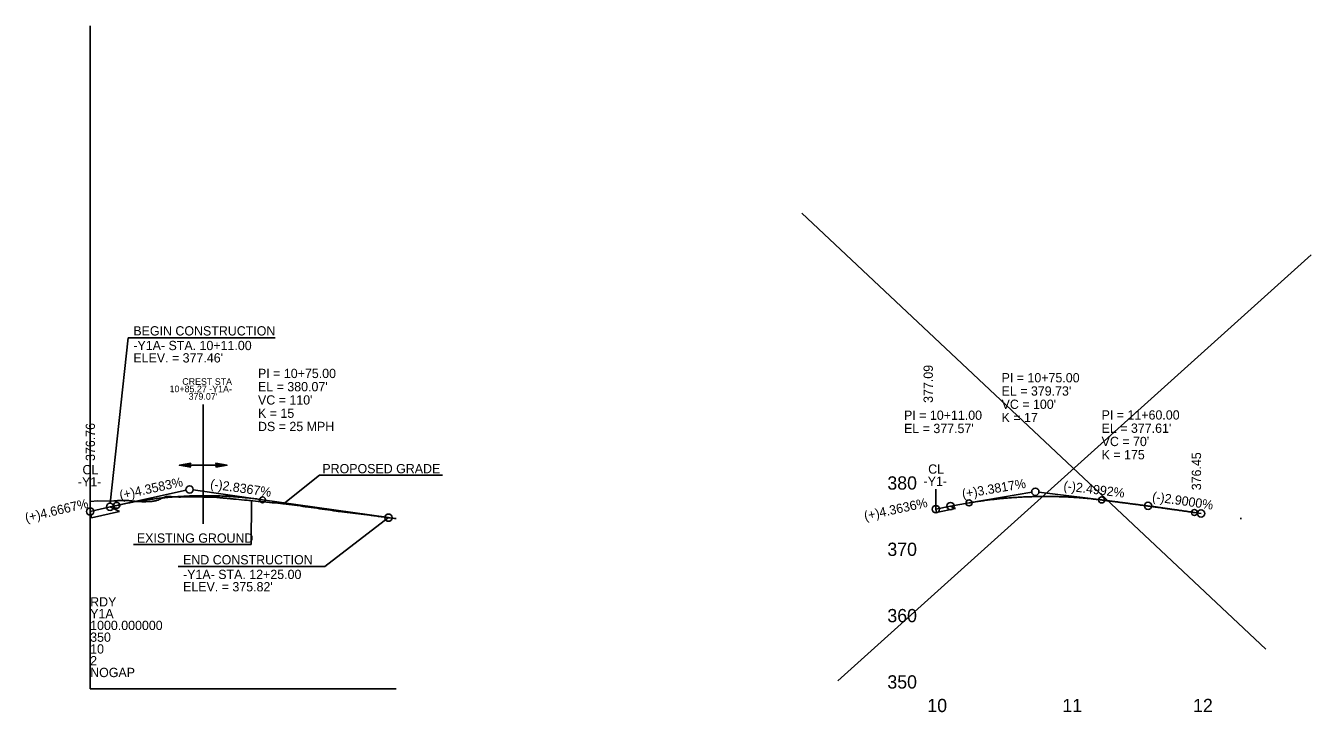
# Model space of a CAD drawing. Extents: x 1625686 to 1640492, y 1161393 to 1175642.
# Drawn here: x 1630156 to 1631125, y 1170769 to 1171286 of the extents above; entities that cross this region are included whole.
import ezdxf

# ---------------------------------------------------------------- set-up
doc = ezdxf.new("R2010")
doc.units = 0
for name, color, linetype in [('Exist Profile Cell', 7, 'Continuous'), ('Exist Vertical Profile Ground Line', 7, 'Continuous'), ('Exist Vertical Profile Horizontal Axis Label Major', 7, 'Continuous'), ('Exist Vertical Profile Vertical Axis Label', 7, 'Continuous'), ('Prop Plan Preparation Crest', 7, 'Continuous'), ('Prop Vertical Profile Curve Label', 7, 'Continuous'), ('Prop Vertical Profile Grade', 7, 'Continuous'), ('Prop Vertical Profile Grade Label', 7, 'Continuous'), ('Prop VPI Label', 7, 'Continuous')]:
    doc.layers.add(name, color=color, linetype=linetype)

msp = doc.modelspace()

# ---------------------------------------------------------------- linework, layer by layer
at = {"layer": 'Exist Profile Cell'}
for q in [(1630204.31, 1171286.24), (1630434.97, 1170786.24), (1630204.31, 1170786.24)]:
    msp.add_line((1630204.31, 1170786.24), q, dxfattribs=at)
at = {"layer": 'Exist Vertical Profile Ground Line'}
for points in [[(1630204.31, 1170927.62), (1630210.19, 1170927.9), (1630220.57, 1170927.84), (1630222.12, 1170927.94), (1630222.92, 1170927.99), (1630223.71, 1170928.04), (1630224.51, 1170928.1), (1630225.3, 1170928.15), (1630225.61, 1170928.17), (1630226.1, 1170928.19), (1630226.89, 1170928.22), (1630227.69, 1170928.25), (1630228.48, 1170928.29), (1630229.28, 1170928.32), (1630230.07, 1170928.35), (1630230.96, 1170928.39), (1630231.66, 1170928.32), (1630232.46, 1170928.23), (1630233.25, 1170928.15), (1630234.05, 1170928.07), (1630234.84, 1170927.98), (1630235.64, 1170927.9), (1630236.43, 1170927.82), (1630237.22, 1170927.73), (1630238.02, 1170927.65), (1630238.4, 1170927.61), (1630238.81, 1170927.6), (1630239.61, 1170927.58), (1630240.4, 1170927.56), (1630241.2, 1170927.53), (1630241.99, 1170927.48), (1630242.79, 1170927.42), (1630243.58, 1170927.38), (1630244.38, 1170927.38), (1630245.17, 1170927.39), (1630245.97, 1170927.39), (1630246.76, 1170927.4), (1630247.56, 1170927.4), (1630248.35, 1170927.4), (1630249.15, 1170927.41), (1630249.54, 1170927.41), (1630249.94, 1170927.47), (1630250.74, 1170927.59), (1630251.53, 1170927.71), (1630252.33, 1170927.83), (1630253.12, 1170927.95), (1630253.92, 1170928.07), (1630254.46, 1170928.15), (1630255.51, 1170928.62), (1630256.3, 1170928.97), (1630257.09, 1170929.32), (1630257.89, 1170929.66), (1630258.68, 1170930.01), (1630259.48, 1170930.35), (1630260.27, 1170930.68), (1630261.07, 1170931.02), (1630261.96, 1170931.35), (1630262.66, 1170931.31), (1630263.45, 1170931.28), (1630264.25, 1170931.24), (1630265.04, 1170931.2), (1630265.84, 1170931.16), (1630266.63, 1170931.13), (1630267.43, 1170931.09), (1630268.22, 1170931.05), (1630269.02, 1170931.02), (1630269.81, 1170930.98), (1630270.61, 1170930.94), (1630271.4, 1170930.91), (1630271.75, 1170930.89), (1630272.14, 1170930.88), (1630272.99, 1170930.94), (1630273.79, 1170930.99), (1630274.67, 1170931.04), (1630275.02, 1170931.06), (1630275.37, 1170931.06), (1630276.17, 1170931.06), (1630276.96, 1170931.05), (1630277.76, 1170931.04), (1630278.55, 1170931.04), (1630279.35, 1170931.03), (1630280.14, 1170931.03), (1630280.94, 1170931.02), (1630281.73, 1170931.01), (1630282.53, 1170931), (1630283.32, 1170931), (1630284.12, 1170930.99), (1630284.91, 1170930.98), (1630285.71, 1170930.97), (1630286.04, 1170930.97), (1630286.5, 1170930.96), (1630287.3, 1170930.95), (1630288.09, 1170930.93), (1630288.89, 1170930.92), (1630289.68, 1170930.91), (1630290.48, 1170930.89), (1630291.27, 1170930.88), (1630292.07, 1170930.87), (1630292.86, 1170930.85), (1630293.65, 1170930.84), (1630294.45, 1170930.82), (1630295.24, 1170930.81), (1630296.04, 1170930.79), (1630296.83, 1170930.78), (1630297.63, 1170930.76), (1630298.52, 1170930.73), (1630299.22, 1170930.67), (1630300.01, 1170930.59), (1630300.81, 1170930.51), (1630301.69, 1170930.42), (1630302.4, 1170930.36), (1630303.19, 1170930.29), (1630303.99, 1170930.22), (1630304.78, 1170930.15), (1630305.58, 1170930.07), (1630306.37, 1170930), (1630307.17, 1170929.93), (1630307.96, 1170929.85), (1630308.76, 1170929.78), (1630309.55, 1170929.7), (1630310.35, 1170929.63), (1630311.14, 1170929.55), (1630311.94, 1170929.48), (1630312.73, 1170929.4), (1630313.52, 1170929.33), (1630314.32, 1170929.25), (1630316.42, 1170929.05), (1630318.51, 1170928.84), (1630320.61, 1170928.64), (1630322.71, 1170928.44), (1630324.02, 1170928.31), (1630324.81, 1170928.23), (1630325.16, 1170928.19), (1630326.91, 1170928.02), (1630329, 1170927.82), (1630331.1, 1170927.62), (1630333.2, 1170927.42), (1630335.3, 1170927.22), (1630337.39, 1170927.02), (1630339.49, 1170926.83), (1630341.59, 1170926.63), (1630343.69, 1170926.43), (1630345.78, 1170926.23), (1630347.88, 1170926.04), (1630349, 1170925.93), (1630349.07, 1170925.93), (1630349.98, 1170925.81), (1630352.08, 1170925.53), (1630354.17, 1170925.26), (1630356.27, 1170924.99), (1630358.37, 1170924.71), (1630360.47, 1170924.42), (1630362.56, 1170924.13), (1630364.66, 1170923.84), (1630366.18, 1170923.64), (1630366.76, 1170923.56), (1630368.86, 1170923.27), (1630370.95, 1170922.98), (1630373.05, 1170922.69), (1630375.15, 1170922.4), (1630377.25, 1170922.11), (1630379.35, 1170921.82), (1630380.76, 1170921.62), (1630381.44, 1170921.52), (1630383.54, 1170921.22), (1630385.64, 1170920.92), (1630387.74, 1170920.61), (1630389.83, 1170920.3), (1630390.27, 1170920.24), (1630391.31, 1170920.06), (1630391.93, 1170919.99), (1630394.03, 1170919.75), (1630396.13, 1170919.5), (1630398.22, 1170919.25), (1630400.32, 1170919), (1630402.42, 1170918.74), (1630404.52, 1170918.49), (1630406.61, 1170918.23), (1630407.02, 1170918.18), (1630408.71, 1170917.96), (1630410.81, 1170917.7), (1630412.91, 1170917.43), (1630415, 1170917.17), (1630416.16, 1170917.02), (1630416.29, 1170917), (1630417.1, 1170916.9), (1630418.22, 1170916.76), (1630419.34, 1170916.62), (1630420.45, 1170916.47), (1630421.57, 1170916.33), (1630422.69, 1170916.18), (1630423.8, 1170916.04), (1630424.92, 1170915.89), (1630426.04, 1170915.75), (1630427.15, 1170915.6), (1630428.27, 1170915.46), (1630429.39, 1170915.31), (1630430.5, 1170915.17), (1630431.62, 1170915.02), (1630432.74, 1170914.9), (1630433.85, 1170914.76), (1630434.97, 1170914.62)], [(1631071.48, 1170914.76), (1631072.6, 1170914.62)]]:
    msp.add_lwpolyline(points, dxfattribs=at)
at = {"layer": 'Prop Plan Preparation Crest'}
for p, q in [((1630289.58, 1170910.79), (1630289.58, 1171000.74)), ((1630289.58, 1170954.88), (1630271.58, 1170954.88)), ((1630289.58, 1170954.88), (1630307.58, 1170954.88))]:
    msp.add_line(p, q, dxfattribs=at)
for points in [[(1630280.15, 1170953.46), (1630271.58, 1170954.88), (1630280.15, 1170956.31), (1630279.08, 1170954.88)], [(1630299.02, 1170953.46), (1630307.58, 1170954.88), (1630299.02, 1170956.31), (1630300.08, 1170954.88)]]:
    msp.add_lwpolyline(points, close=True, dxfattribs=at)
at = {"layer": 'Prop Vertical Profile Curve Label'}
for p, q in [((1630204.31, 1170921.24), (1630204.31, 1170936.44)), ((1630842.08, 1170921.69), (1630842.08, 1170936.89))]:
    msp.add_line(p, q, dxfattribs=at)
for centre in [(1630224.31, 1170924.63), (1630334.31, 1170928.82), (1630867.08, 1170926.46), (1630967.08, 1170928.67), (1631037.08, 1170919.22)]:
    msp.add_circle(centre, 2.25, dxfattribs=at)
at = {"layer": 'Prop Vertical Profile Grade'}
for p, q in [((1630334.31, 1170928.82), (1630429.31, 1170915.34)), ((1630853.08, 1170924.09), (1630867.08, 1170926.46)), ((1630204.31, 1170920.04), (1630219.31, 1170923.54)), ((1630219.31, 1170923.54), (1630224.31, 1170924.63)), ((1630842.08, 1170921.69), (1630853.08, 1170924.09)), ((1631037.08, 1170919.22), (1631042.08, 1170918.49))]:
    msp.add_line(p, q, dxfattribs=at)
for points in [[(1630224.31, 1170924.63), (1630226.51, 1170925.1), (1630228.71, 1170925.56), (1630230.91, 1170926), (1630233.11, 1170926.42), (1630235.31, 1170926.83), (1630237.51, 1170927.22), (1630239.71, 1170927.6), (1630241.91, 1170927.96), (1630244.11, 1170928.31), (1630246.31, 1170928.63), (1630248.51, 1170928.95), (1630250.71, 1170929.24), (1630252.91, 1170929.53), (1630255.11, 1170929.79), (1630257.31, 1170930.04), (1630259.51, 1170930.28), (1630261.71, 1170930.49), (1630263.91, 1170930.7), (1630266.11, 1170930.88), (1630268.31, 1170931.05), (1630270.51, 1170931.21), (1630272.71, 1170931.35), (1630274.91, 1170931.47), (1630277.11, 1170931.58), (1630279.31, 1170931.67), (1630281.51, 1170931.75), (1630283.71, 1170931.81), (1630285.91, 1170931.85), (1630288.11, 1170931.88), (1630290.31, 1170931.89), (1630292.51, 1170931.89), (1630294.71, 1170931.87), (1630296.91, 1170931.83), (1630299.11, 1170931.78), (1630301.31, 1170931.72), (1630303.51, 1170931.63), (1630305.71, 1170931.54), (1630307.91, 1170931.42), (1630310.11, 1170931.29), (1630312.31, 1170931.15), (1630314.51, 1170930.98), (1630316.71, 1170930.81), (1630318.91, 1170930.61), (1630321.11, 1170930.4), (1630323.31, 1170930.18), (1630325.51, 1170929.94), (1630327.71, 1170929.68), (1630329.91, 1170929.41), (1630332.11, 1170929.12), (1630334.31, 1170928.82)], [(1630867.08, 1170926.46), (1630869.08, 1170926.79), (1630871.08, 1170927.11), (1630873.08, 1170927.42), (1630875.08, 1170927.72), (1630877.08, 1170928), (1630879.08, 1170928.28), (1630881.08, 1170928.54), (1630883.08, 1170928.79), (1630885.08, 1170929.03), (1630887.08, 1170929.25), (1630889.08, 1170929.47), (1630891.08, 1170929.67), (1630893.08, 1170929.86), (1630895.08, 1170930.04), (1630897.08, 1170930.21), (1630899.08, 1170930.36), (1630901.08, 1170930.51), (1630903.08, 1170930.64), (1630905.08, 1170930.76), (1630907.08, 1170930.87), (1630909.08, 1170930.97), (1630911.08, 1170931.05), (1630913.08, 1170931.13), (1630915.08, 1170931.19), (1630917.08, 1170931.24), (1630919.08, 1170931.28), (1630921.08, 1170931.3), (1630923.08, 1170931.32), (1630925.08, 1170931.32), (1630927.08, 1170931.31), (1630929.08, 1170931.29), (1630931.08, 1170931.26), (1630933.08, 1170931.21), (1630935.08, 1170931.16), (1630937.08, 1170931.09), (1630939.08, 1170931.01), (1630941.08, 1170930.92), (1630943.08, 1170930.82), (1630945.08, 1170930.7), (1630947.08, 1170930.58), (1630949.08, 1170930.44), (1630951.08, 1170930.29), (1630953.08, 1170930.13), (1630955.08, 1170929.95), (1630957.08, 1170929.77), (1630959.08, 1170929.57), (1630961.08, 1170929.36), (1630963.08, 1170929.14), (1630965.08, 1170928.91), (1630967.08, 1170928.67)], [(1630967.08, 1170928.67), (1630968.48, 1170928.49), (1630969.88, 1170928.31), (1630971.28, 1170928.14), (1630972.68, 1170927.96), (1630974.08, 1170927.78), (1630975.48, 1170927.61), (1630976.88, 1170927.43), (1630978.28, 1170927.25), (1630979.68, 1170927.07), (1630981.08, 1170926.89), (1630982.48, 1170926.71), (1630983.88, 1170926.53), (1630985.28, 1170926.34), (1630986.68, 1170926.16), (1630988.08, 1170925.98), (1630989.48, 1170925.79), (1630990.88, 1170925.61), (1630992.28, 1170925.43), (1630993.68, 1170925.24), (1630995.08, 1170925.05), (1630996.48, 1170924.87), (1630997.88, 1170924.68), (1630999.28, 1170924.49), (1631000.68, 1170924.31), (1631002.08, 1170924.12), (1631003.48, 1170923.93), (1631004.88, 1170923.74), (1631006.28, 1170923.55), (1631007.68, 1170923.36), (1631009.08, 1170923.16), (1631010.48, 1170922.97), (1631011.88, 1170922.78), (1631013.28, 1170922.59), (1631014.68, 1170922.39), (1631016.08, 1170922.2), (1631017.48, 1170922), (1631018.88, 1170921.81), (1631020.28, 1170921.61), (1631021.68, 1170921.42), (1631023.08, 1170921.22), (1631024.48, 1170921.02), (1631025.88, 1170920.82), (1631027.28, 1170920.62), (1631028.68, 1170920.42), (1631030.08, 1170920.22), (1631031.48, 1170920.02), (1631032.88, 1170919.82), (1631034.28, 1170919.62), (1631035.68, 1170919.42), (1631037.08, 1170919.22)]]:
    msp.add_spline(points, degree=3, dxfattribs=at)
at = {"layer": 'Prop Vertical Profile Grade Label'}
for p, q in [((1630741, 1171144.82), (1631090.92, 1170816.15)), ((1631125.2, 1171113.38), (1630768.23, 1170792.38)), ((1630219.31, 1170926.29), (1630233.06, 1171050.97)), ((1630233.06, 1171050.97), (1630343.74, 1171050.97)), ((1630205.43, 1170915.21), (1630226.43, 1170920.08)), ((1630842.63, 1170919.18), (1630842.08, 1170921.69)), ((1630842.63, 1170919.18), (1630856.97, 1170922.31)), ((1630853.08, 1170924.09), (1630856.97, 1170922.31)), ((1630429.31, 1170915.34), (1630381.24, 1170878.39)), ((1630270.55, 1170878.39), (1630381.24, 1170878.39))]:
    msp.add_line(p, q, dxfattribs=at)
at = {"layer": 'Prop VPI Label'}
for p, q in [((1630377.35, 1170947.36), (1630351.12, 1170926.43)), ((1630469.9, 1170947.36), (1630377.35, 1170947.36)), ((1630224.31, 1170924.63), (1630276.63, 1170936.03)), ((1630334.31, 1170928.82), (1630282.04, 1170936.23)), ((1630325.62, 1170894.99), (1630326.03, 1170928.11)), ((1630867.08, 1170926.46), (1630914.37, 1170934.46)), ((1630967.08, 1170928.67), (1630919.81, 1170934.57)), ((1630967.08, 1170928.67), (1630999.35, 1170924.63)), ((1630205.43, 1170915.21), (1630204.31, 1170920.04)), ((1630226.43, 1170920.08), (1630219.31, 1170923.54)), ((1631037.08, 1170919.22), (1631004.8, 1170923.9)), ((1630325.62, 1170894.99), (1630237.01, 1170894.99))]:
    msp.add_line(p, q, dxfattribs=at)
for centre in [(1630279.31, 1170936.62), (1630917.08, 1170934.91), (1630219.31, 1170923.54), (1630853.08, 1170924.09), (1631002.08, 1170924.29), (1630204.31, 1170920.04), (1630429.31, 1170915.34), (1630429.31, 1170915.34), (1630842.08, 1170921.69), (1631042.08, 1170918.49)]:
    msp.add_circle(centre, 2.75, dxfattribs=at)

# ---------------------------------------------------------------- texts
at = {"layer": 'Exist Profile Cell'}
for s, p in [('RDY', (1630204.31, 1170848.36)), ('Y1A', (1630204.31, 1170839.49)), ('350', (1630204.31, 1170821.74)), ('1000.000000', (1630204.31, 1170830.61)), ('10', (1630204.31, 1170812.86)), ('2', (1630204.31, 1170803.99)), ('NOGAP', (1630204.31, 1170795.12))]:
    msp.add_text(s, height=7, dxfattribs=at).set_placement(p)
at = {"layer": 'Exist Vertical Profile Horizontal Axis Label Major'}
for s, p in [('10', (1630835.66, 1170768.74)), ('11', (1630937.5, 1170768.74)), ('12', (1631036.05, 1170768.74))]:
    msp.add_text(s, height=10, dxfattribs=at).set_placement(p)
at = {"layer": 'Exist Vertical Profile Vertical Axis Label'}
for s, p in [('380', (1630805.51, 1170936.49)), ('370', (1630805.51, 1170886.49)), ('360', (1630805.51, 1170836.49)), ('350', (1630805.51, 1170786.49))]:
    msp.add_text(s, height=10, dxfattribs=at).set_placement(p)
at = {"layer": 'Prop Plan Preparation Crest'}
for s, p in [('10+85.27 -Y1A-', (1630264.17, 1171009.96)), ('CREST STA', (1630273.77, 1171015.52)), ("379.07'", (1630278.54, 1171004.28))]:
    msp.add_text(s, height=5, rotation=359.75466, dxfattribs=at).set_placement(p)
at = {"layer": 'Prop Vertical Profile Curve Label'}
for s, p in [("VC = 110'", (1630330.88, 1171000.6)), ("VC = 100'", (1630891.65, 1170997.35)), ('K = 15', (1630330.88, 1170990.6)), ('K = 17', (1630891.65, 1170987.35)), ('DS = 25 MPH', (1630330.88, 1170980.6)), ("VC = 70'", (1630967.08, 1170969.29)), ('K = 175', (1630967.08, 1170959.29))]:
    msp.add_text(s, height=7, dxfattribs=at).set_placement(p)
at = {"layer": 'Prop Vertical Profile Grade Label'}
for s, rotation, p in [('(+)4.3583%', 12.29351, (1630227.22, 1170928.8)), ('(-)2.8367%', 351.92739, (1630294.51, 1170937.49)), ('(+)3.3817%', 9.59719, (1630862.41, 1170929.77)), ('(-)2.4992%', 352.87726, (1630938.03, 1170936.12)), ('(+)4.6667%', 13.13402, (1630156.07, 1170911.86)), ('(+)4.3636%', 12.30802, (1630788.75, 1170913.13)), ('(-)2.9000%', 351.74961, (1631004.87, 1170927.95))]:
    msp.add_text(s, height=7, rotation=rotation, dxfattribs=at).set_placement(p)
at = {"layer": 'Prop VPI Label'}
for s, p in [('BEGIN CONSTRUCTION', (1630236.87, 1171052.68)), ('-Y1A- STA. 10+11.00', (1630236.87, 1171041.65)), ("ELEV. = 377.46'", (1630236.87, 1171032.33)), ('PI = 10+75.00', (1630330.88, 1171020.6)), ('PI = 10+75.00', (1630891.65, 1171017.35)), ("EL = 380.07'", (1630330.88, 1171010.6)), ("EL = 379.73'", (1630891.65, 1171007.35)), ('PI = 10+11.00', (1630818.08, 1170989.09)), ('PI = 11+60.00', (1630967.08, 1170989.29)), ("EL = 377.57'", (1630818.08, 1170979.09)), ("EL = 377.61'", (1630967.08, 1170979.29)), ('CL', (1630198.51, 1170948.04)), ('PROPOSED GRADE', (1630379.41, 1170948.81)), ('CL', (1630836.28, 1170948.49)), ('-Y1-', (1630195.05, 1170938.86)), ('-Y1-', (1630832.81, 1170939.31)), ('EXISTING GROUND', (1630239.54, 1170896.43)), ('END CONSTRUCTION', (1630274.37, 1170880.1)), ('-Y1A- STA. 12+25.00', (1630274.37, 1170869.06)), ("ELEV. = 375.82'", (1630274.37, 1170859.75))]:
    msp.add_text(s, height=7, dxfattribs=at).set_placement(p)
for s, p in [('377.09', (1630839.81, 1171001.87)), ('376.76', (1630207.93, 1170958.07)), ('376.45', (1631042.08, 1170935.99))]:
    msp.add_text(s, height=7, rotation=90, dxfattribs=at).set_placement(p)

doc.saveas('drawing.dxf')
